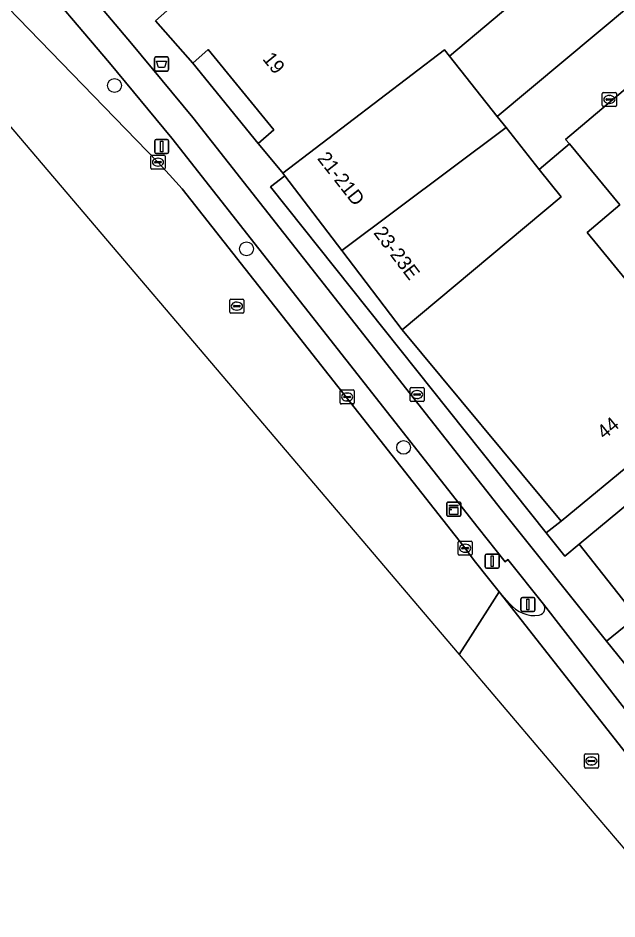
# Model space of a CAD drawing. Extents: x 161087 to 161926, y 382572 to 383873.
# Drawn here: x 161275.9 to 161318.5, y 383048.2 to 383112.2 of the extents above; entities that cross this region are included whole.
import ezdxf

# ---------------------------------------------------------------- set-up
doc = ezdxf.new("R2010")
doc.units = 0
for name, color, linetype in [('IMGEO_Afvalbak', 7, 'Continuous'), ('IMGEO_Berm_groen', 7, 'Continuous'), ('IMGEO_Boom', 7, 'Continuous'), ('IMGEO_Brandkraan', 7, 'Continuous'), ('IMGEO_Fietspad_gesloten', 7, 'Continuous'), ('IMGEO_Kast', 7, 'Continuous'), ('IMGEO_Kolk', 7, 'Continuous'), ('IMGEO_Lichtmast', 7, 'Continuous'), ('IMGEO_Pand', 7, 'Continuous'), ('IMGEO_Pand_nummerreeks', 7, 'Continuous'), ('IMGEO_Pand_overbouw', 7, 'Continuous'), ('IMGEO_Rijbaan_lokaal_gesloten', 7, 'Continuous'), ('IMGEO_Rijbaan_lokaal_open', 7, 'Continuous'), ('IMGEO_Rioolput', 7, 'Continuous'), ('IMGEO_Terreindeel_open', 7, 'Continuous'), ('IMGEO_Verkeersregelinstallatiepaal', 7, 'Continuous'), ('IMGEO_Voetgangersgebied_open', 7, 'Continuous'), ('IMGEO_Voetpad_open', 7, 'Continuous')]:
    doc.layers.add(name, color=color, linetype=linetype)

msp = doc.modelspace()

# ---------------------------------------------------------------- linework, layer by layer
at = {"layer": 'IMGEO_Afvalbak'}
for p, q in [((161285.712, 383109.459), (161286.502, 383109.459)), ((161286.502, 383109.459), (161285.712, 383109.459)), ((161285.612, 383108.559), (161285.612, 383109.359)), ((161285.612, 383109.359), (161285.612, 383108.559)), ((161286.602, 383109.359), (161286.602, 383108.559)), ((161286.602, 383108.559), (161286.602, 383109.359)), ((161286.502, 383108.459), (161285.712, 383108.459)), ((161285.712, 383108.459), (161286.502, 383108.459))]:
    msp.add_line(p, q, dxfattribs=at)
msp.add_lwpolyline([(161285.755, 383109.173), (161286.459, 383109.173), (161286.31, 383108.703), (161285.904, 383108.703), (161285.755, 383109.173)], dxfattribs=at)
for centre, start, end in [((161285.712, 383109.359), 90, 180), ((161285.712, 383109.359), 90, 180), ((161286.502, 383109.359), 0, 90), ((161286.502, 383109.359), 360, 90), ((161285.712, 383108.559), 180, 270), ((161285.712, 383108.559), 180, 270), ((161286.502, 383108.559), 270, 0), ((161286.502, 383108.559), 270, 0)]:
    msp.add_arc(centre, 0.1, start, end, dxfattribs=at)
at = {"layer": 'IMGEO_Berm_groen'}
for points in [[(161252.834, 383141.869), (161249.891, 383139.013), (161250.747, 383138.142), (161260.112, 383128.472), (161274.401, 383113.771), (161285.856, 383101.979), (161286.681, 383101.086), (161287.586, 383100.08), (161307.615, 383074.667), (161308.345, 383073.655), (161309.464, 383072.265), (161310.134, 383071.432), (161310.872, 383070.614)], [(161313.28, 383070.545), (161310.735, 383073.723), (161310.56, 383073.578), (161308.644, 383075.982), (161286.834, 383103.696), (161282.397, 383109.044), (161276.591, 383115.882)]]:
    msp.add_lwpolyline(points, dxfattribs=at)
for centre, radius, start, end in [((161312.644, 383071.988), 2.242, 217.80063, 278.38962), ((161312.872, 383070.249), 0.504, 344.59382, 35.96896), ((161312.889, 383070.252), 0.489, 279.70174, 343.73054)]:
    msp.add_arc(centre, radius, start, end, dxfattribs=at)
at = {"layer": 'IMGEO_Boom'}
for centre in [(161282.763, 383107.431), (161292.154, 383095.819), (161303.331, 383081.699)]:
    msp.add_circle(centre, 0.489, dxfattribs=at)
at = {"layer": 'IMGEO_Brandkraan'}
for p, q in [((161303.786, 383085.034), (161303.786, 383085.886)), ((161303.861, 383085.96), (161304.713, 383085.96)), ((161304.274, 383085.74), (161304.299, 383085.74)), ((161304.787, 383085.886), (161304.787, 383085.034)), ((161304.045, 383085.454), (161304.045, 383085.466)), ((161304.483, 383085.417), (161304.085, 383085.417)), ((161304.088, 383085.503), (161304.486, 383085.503)), ((161304.297, 383085.18), (161304.272, 383085.18)), ((161304.529, 383085.466), (161304.529, 383085.454)), ((161304.713, 383084.96), (161303.861, 383084.96))]:
    msp.add_line(p, q, dxfattribs=at)
for points in [[(161303.786, 383085.034), (161303.786, 383085.886)], [(161303.861, 383085.96), (161304.713, 383085.96)], [(161304.787, 383085.886), (161304.787, 383085.034)], [(161304.713, 383084.96), (161303.861, 383084.96)]]:
    msp.add_lwpolyline(points, dxfattribs=at)
for centre, radius, start, end in [((161303.863, 383085.884), 0.0765, 91.55205, 178.44795), ((161303.863, 383085.884), 0.0765, 91.55205, 178.44795), ((161304.711, 383085.884), 0.0765, 1.55205, 88.44795), ((161304.711, 383085.884), 0.0765, 1.55205, 88.44795), ((161304.085, 383085.463), 0.0403, 85.87752, 175.75265), ((161304.082, 383085.453), 0.0366, 178.93798, 274.71019), ((161304.486, 383085.46), 0.043, 264.86636, 352.45326), ((161304.49, 383085.465), 0.0386, 1.73085, 96.63898), ((161303.863, 383085.036), 0.0765, 181.55205, 268.44795), ((161303.863, 383085.036), 0.0765, 181.55205, 268.44795), ((161304.711, 383085.036), 0.0765, 271.55205, 358.44795), ((161304.711, 383085.036), 0.0765, 271.55205, 358.44795)]:
    msp.add_arc(centre, radius, start, end, dxfattribs=at)
for centre, major_axis, ratio, start_param, end_param in [((161304.273, 383085.46), (-0.387, 0.002), 0.722429, 4.712389, 7.853982), ((161304.298, 383085.46), (-0.39, 0.002), 0.717154, 1.570796, 4.712389)]:
    msp.add_ellipse(centre, major_axis=major_axis, ratio=ratio, start_param=start_param, end_param=end_param, dxfattribs=at)
at = {"layer": 'IMGEO_Fietspad_gesloten'}
msp.add_lwpolyline([(161276.591, 383115.882), (161282.397, 383109.044), (161286.834, 383103.696), (161308.644, 383075.982), (161310.56, 383073.578), (161310.735, 383073.723), (161313.28, 383070.545), (161323.08, 383057.943), (161324.746, 383059.32), (161317.769, 383067.924), (161310.282, 383077.252), (161288.336, 383105.145), (161283.981, 383110.422), (161278.277, 383117.164)], dxfattribs=at)
at = {"layer": 'IMGEO_Kast'}
for p, q in [((161306.399, 383076.891), (161306.399, 383077.732)), ((161306.399, 383077.732), (161306.399, 383076.891)), ((161306.474, 383077.816), (161307.315, 383077.816)), ((161307.315, 383077.816), (161306.474, 383077.816)), ((161307.399, 383077.741), (161307.399, 383076.9)), ((161307.399, 383076.9), (161307.399, 383077.741)), ((161307.324, 383076.816), (161306.483, 383076.816)), ((161306.483, 383076.816), (161307.324, 383076.816))]:
    msp.add_line(p, q, dxfattribs=at)
for points in [[(161306.594, 383077.606), (161307.194, 383077.606), (161307.194, 383077.521), (161306.594, 383077.521), (161306.594, 383077.606)], [(161306.594, 383077.431), (161307.194, 383077.431), (161307.194, 383076.942), (161306.594, 383076.942), (161306.594, 383077.431)]]:
    msp.add_lwpolyline(points, dxfattribs=at)
msp.add_circle((161306.678, 383077.28), 0.0377, dxfattribs=at)
for centre, start, end in [((161306.477, 383077.738), 92.4484, 184.28452), ((161306.477, 383077.738), 92.4484, 184.28452), ((161307.321, 383077.738), 2.4484, 94.28452), ((161307.321, 383077.738), 2.4484, 94.28452), ((161306.477, 383076.894), 182.4484, 274.28452), ((161306.477, 383076.894), 182.4484, 274.28452), ((161307.321, 383076.894), 272.4484, 4.28452), ((161307.321, 383076.894), 272.4484, 4.28452)]:
    msp.add_arc(centre, 0.0779, start, end, dxfattribs=at)
at = {"layer": 'IMGEO_Kolk'}
for p, q in [((161317.467, 383106.014), (161317.467, 383106.866)), ((161317.542, 383106.94), (161318.394, 383106.94)), ((161318.468, 383106.866), (161318.468, 383106.014)), ((161317.726, 383106.434), (161317.726, 383106.446)), ((161318.164, 383106.397), (161317.766, 383106.397)), ((161317.769, 383106.483), (161318.167, 383106.483)), ((161317.955, 383106.72), (161317.98, 383106.72)), ((161318.21, 383106.446), (161318.21, 383106.434)), ((161318.394, 383105.94), (161317.542, 383105.94)), ((161317.978, 383106.16), (161317.953, 383106.16)), ((161285.355, 383101.553), (161285.355, 383102.405)), ((161285.43, 383102.479), (161286.282, 383102.479)), ((161286.356, 383102.405), (161286.356, 383101.553)), ((161285.614, 383101.973), (161285.614, 383101.985)), ((161286.052, 383101.936), (161285.654, 383101.936)), ((161285.657, 383102.022), (161286.055, 383102.022)), ((161285.843, 383102.259), (161285.868, 383102.259)), ((161286.098, 383101.985), (161286.098, 383101.973)), ((161286.282, 383101.479), (161285.43, 383101.479)), ((161285.866, 383101.699), (161285.841, 383101.699)), ((161298.887, 383085.788), (161299.739, 383085.788)), ((161298.812, 383084.862), (161298.812, 383085.714)), ((161299.071, 383085.282), (161299.071, 383085.294)), ((161299.509, 383085.245), (161299.111, 383085.245)), ((161299.114, 383085.331), (161299.512, 383085.331)), ((161299.3, 383085.568), (161299.325, 383085.568)), ((161299.555, 383085.294), (161299.555, 383085.282)), ((161299.813, 383085.714), (161299.813, 383084.862)), ((161299.739, 383084.788), (161298.887, 383084.788)), ((161299.323, 383085.008), (161299.298, 383085.008)), ((161307.205, 383074.106), (161307.205, 383074.958)), ((161307.28, 383075.032), (161308.132, 383075.032)), ((161308.206, 383074.958), (161308.206, 383074.106)), ((161307.464, 383074.526), (161307.464, 383074.538)), ((161307.902, 383074.489), (161307.504, 383074.489)), ((161307.507, 383074.575), (161307.905, 383074.575)), ((161307.716, 383074.252), (161307.691, 383074.252)), ((161307.693, 383074.812), (161307.718, 383074.812)), ((161307.948, 383074.538), (161307.948, 383074.526)), ((161308.132, 383074.032), (161307.28, 383074.032))]:
    msp.add_line(p, q, dxfattribs=at)
for points in [[(161317.467, 383106.014), (161317.467, 383106.866)], [(161317.542, 383106.94), (161318.394, 383106.94)], [(161318.468, 383106.866), (161318.468, 383106.014)], [(161318.394, 383105.94), (161317.542, 383105.94)], [(161285.355, 383101.553), (161285.355, 383102.405)], [(161285.43, 383102.479), (161286.282, 383102.479)], [(161286.356, 383102.405), (161286.356, 383101.553)], [(161286.282, 383101.479), (161285.43, 383101.479)], [(161298.887, 383085.788), (161299.739, 383085.788)], [(161298.812, 383084.862), (161298.812, 383085.714)], [(161299.813, 383085.714), (161299.813, 383084.862)], [(161299.739, 383084.788), (161298.887, 383084.788)], [(161307.205, 383074.106), (161307.205, 383074.958)], [(161307.28, 383075.032), (161308.132, 383075.032)], [(161308.206, 383074.958), (161308.206, 383074.106)], [(161308.132, 383074.032), (161307.28, 383074.032)]]:
    msp.add_lwpolyline(points, dxfattribs=at)
for centre, radius, start, end in [((161317.544, 383106.864), 0.0765, 91.55205, 178.44795), ((161317.544, 383106.864), 0.0765, 91.55205, 178.44795), ((161318.392, 383106.864), 0.0765, 1.55205, 88.44795), ((161318.392, 383106.864), 0.0765, 1.55205, 88.44795), ((161317.766, 383106.443), 0.0403, 85.87752, 175.75265), ((161317.763, 383106.433), 0.0366, 178.93798, 274.71019), ((161318.167, 383106.44), 0.043, 264.86636, 352.45326), ((161318.171, 383106.445), 0.0386, 1.73085, 96.63898), ((161317.544, 383106.016), 0.0765, 181.55205, 268.44795), ((161317.544, 383106.016), 0.0765, 181.55205, 268.44795), ((161318.392, 383106.016), 0.0765, 271.55205, 358.44795), ((161318.392, 383106.016), 0.0765, 271.55205, 358.44795), ((161285.432, 383102.403), 0.0765, 91.55205, 178.44795), ((161285.432, 383102.403), 0.0765, 91.55205, 178.44795), ((161286.28, 383102.403), 0.0765, 1.55205, 88.44795), ((161286.28, 383102.403), 0.0765, 1.55205, 88.44795), ((161285.654, 383101.982), 0.0403, 85.87752, 175.75265), ((161285.651, 383101.972), 0.0366, 178.93798, 274.71019), ((161286.055, 383101.979), 0.043, 264.86636, 352.45326), ((161286.059, 383101.984), 0.0386, 1.73085, 96.63898), ((161285.432, 383101.555), 0.0765, 181.55205, 268.44795), ((161285.432, 383101.555), 0.0765, 181.55205, 268.44795), ((161286.28, 383101.555), 0.0765, 271.55205, 358.44795), ((161286.28, 383101.555), 0.0765, 271.55205, 358.44795), ((161298.889, 383085.712), 0.0765, 91.55205, 178.44795), ((161298.889, 383085.712), 0.0765, 91.55205, 178.44795), ((161299.737, 383085.712), 0.0765, 1.55205, 88.44795), ((161299.737, 383085.712), 0.0765, 1.55205, 88.44795), ((161299.111, 383085.291), 0.0403, 85.87752, 175.75265), ((161299.108, 383085.281), 0.0366, 178.93798, 274.71019), ((161299.512, 383085.288), 0.043, 264.86636, 352.45326), ((161299.516, 383085.293), 0.0386, 1.73085, 96.63898), ((161298.889, 383084.864), 0.0765, 181.55205, 268.44795), ((161298.889, 383084.864), 0.0765, 181.55205, 268.44795), ((161299.737, 383084.864), 0.0765, 271.55205, 358.44795), ((161299.737, 383084.864), 0.0765, 271.55205, 358.44795), ((161307.282, 383074.956), 0.0765, 91.55205, 178.44795), ((161307.282, 383074.956), 0.0765, 91.55205, 178.44795), ((161308.13, 383074.956), 0.0765, 1.55205, 88.44795), ((161308.13, 383074.956), 0.0765, 1.55205, 88.44795), ((161307.504, 383074.535), 0.0403, 85.87752, 175.75265), ((161307.501, 383074.525), 0.0366, 178.93798, 274.71019), ((161307.905, 383074.532), 0.043, 264.86636, 352.45326), ((161307.909, 383074.537), 0.0386, 1.73085, 96.63898), ((161307.282, 383074.108), 0.0765, 181.55205, 268.44795), ((161307.282, 383074.108), 0.0765, 181.55205, 268.44795), ((161308.13, 383074.108), 0.0765, 271.55205, 358.44795), ((161308.13, 383074.108), 0.0765, 271.55205, 358.44795)]:
    msp.add_arc(centre, radius, start, end, dxfattribs=at)
for centre, major_axis, ratio, start_param, end_param in [((161317.954, 383106.44), (-0.387, 0.002), 0.722429, 4.712389, 7.853982), ((161317.979, 383106.44), (-0.39, 0.002), 0.717154, 1.570796, 4.712389), ((161285.842, 383101.979), (-0.387, 0.002), 0.722429, 4.712389, 7.853982), ((161285.867, 383101.979), (-0.39, 0.002), 0.717154, 1.570796, 4.712389), ((161299.299, 383085.288), (-0.387, 0.002), 0.722429, 4.712389, 7.853982), ((161299.324, 383085.288), (-0.39, 0.002), 0.717154, 1.570796, 4.712389), ((161307.692, 383074.532), (-0.387, 0.002), 0.722429, 4.712389, 7.853982), ((161307.717, 383074.532), (-0.39, 0.002), 0.717154, 1.570796, 4.712389)]:
    msp.add_ellipse(centre, major_axis=major_axis, ratio=ratio, start_param=start_param, end_param=end_param, dxfattribs=at)
at = {"layer": 'IMGEO_Lichtmast'}
for p, q in [((161285.625, 383102.698), (161285.625, 383103.498)), ((161285.625, 383103.498), (161285.625, 383102.698)), ((161285.725, 383103.598), (161286.515, 383103.598)), ((161286.515, 383103.598), (161285.725, 383103.598)), ((161286.615, 383103.498), (161286.615, 383102.698)), ((161286.615, 383102.698), (161286.615, 383103.498)), ((161286.515, 383102.598), (161285.725, 383102.598)), ((161285.725, 383102.598), (161286.515, 383102.598)), ((161309.135, 383073.209), (161309.135, 383074.009)), ((161309.135, 383074.009), (161309.135, 383073.209)), ((161309.235, 383074.109), (161310.025, 383074.109)), ((161310.025, 383074.109), (161309.235, 383074.109)), ((161310.125, 383074.009), (161310.125, 383073.209)), ((161310.125, 383073.209), (161310.125, 383074.009)), ((161310.025, 383073.109), (161309.235, 383073.109)), ((161309.235, 383073.109), (161310.025, 383073.109))]:
    msp.add_line(p, q, dxfattribs=at)
for points in [[(161286.045, 383103.473), (161286.195, 383103.473), (161286.195, 383102.723), (161286.045, 383102.723), (161286.045, 383103.473)], [(161309.555, 383073.984), (161309.705, 383073.984), (161309.705, 383073.234), (161309.555, 383073.234), (161309.555, 383073.984)]]:
    msp.add_lwpolyline(points, dxfattribs=at)
for centre, start, end in [((161285.725, 383103.498), 90, 180), ((161285.725, 383103.498), 90, 180), ((161286.515, 383103.498), 0, 90), ((161286.515, 383103.498), 360, 90), ((161285.725, 383102.698), 180, 270), ((161285.725, 383102.698), 180, 270), ((161286.515, 383102.698), 270, 0), ((161286.515, 383102.698), 270, 0), ((161309.235, 383074.009), 90, 180), ((161309.235, 383074.009), 90, 180), ((161310.025, 383074.009), 0, 90), ((161310.025, 383074.009), 360, 90), ((161309.235, 383073.209), 180, 270), ((161309.235, 383073.209), 180, 270), ((161310.025, 383073.209), 270, 0), ((161310.025, 383073.209), 270, 0)]:
    msp.add_arc(centre, 0.1, start, end, dxfattribs=at)
at = {"layer": 'IMGEO_Pand'}
for points in [[(161294.742, 383101.191), (161306.233, 383109.974), (161306.597, 383109.514), (161315.91, 383117.352), (161328.147, 383127.651), (161321.746, 383135.741), (161318.155, 383140.007), (161303.657, 383127.806), (161297.243, 383122.411), (161296.75, 383123.041), (161284.685, 383113.393), (161285.039, 383113), (161286.136, 383113.965), (161286.895, 383113.101), (161285.682, 383112.035), (161288.325, 383109.028), (161289.427, 383109.997), (161294.094, 383104.286), (161292.975, 383103.318), (161294.672, 383101.283)], [(161325.68, 383085.643), (161336.573, 383094.624), (161323.371, 383110.78), (161314.857, 383103.599), (161315.131, 383103.273), (161318.705, 383098.955), (161316.388, 383096.985)], [(161294.742, 383101.191), (161294.883, 383101.006), (161298.925, 383095.704), (161310.619, 383104.438), (161309.985, 383105.238), (161306.597, 383109.514), (161306.233, 383109.974)], [(161298.925, 383095.704), (161303.223, 383090.065), (161314.545, 383099.513), (161312.979, 383101.462), (161310.619, 383104.438)], [(161325.68, 383085.643), (161316.388, 383096.985), (161318.705, 383098.955), (161315.131, 383103.273), (161312.979, 383101.462), (161314.545, 383099.513), (161303.223, 383090.065), (161314.528, 383076.448)]]:
    msp.add_lwpolyline(points, close=True, dxfattribs=at)
at = {"layer": 'IMGEO_Pand_overbouw'}
msp.add_lwpolyline([(161292.975, 383103.318), (161294.094, 383104.286), (161289.427, 383109.997), (161288.325, 383109.028)], close=True, dxfattribs=at)
at = {"layer": 'IMGEO_Rijbaan_lokaal_gesloten'}
msp.add_lwpolyline([(161307.272, 383066.988), (161308.081, 383068.244), (161310.134, 383071.432), (161309.464, 383072.265), (161308.345, 383073.655), (161307.615, 383074.667), (161287.586, 383100.08), (161286.681, 383101.086), (161285.856, 383101.979), (161274.401, 383113.771), (161260.112, 383128.472), (161250.747, 383138.142), (161249.891, 383139.013), (161245.035, 383144.043), (161237.305, 383152.019), (161236.492, 383152.832), (161235.276, 383151.613), (161307.272, 383066.988)], dxfattribs=at)
msp.add_lwpolyline([(161307.272, 383066.988), (161316.471, 383056.176), (161319.897, 383052.149), (161322.958, 383048.175), (161323.369, 383048.79), (161325.438, 383051.889), (161323.275, 383054.641), (161322.567, 383055.613), (161310.134, 383071.432), (161308.081, 383068.244)], close=True, dxfattribs=at)
at = {"layer": 'IMGEO_Rijbaan_lokaal_open'}
msp.add_lwpolyline([(161309.985, 383105.238), (161310.619, 383104.438), (161312.979, 383101.462), (161315.131, 383103.273), (161314.857, 383103.599), (161323.371, 383110.78), (161328.949, 383115.484), (161334.699, 383120.333), (161331.884, 383123.579), (161319.475, 383113.135)], close=True, dxfattribs=at)
msp.add_lwpolyline([(161362.829, 383095.814), (161364.77, 383097.35), (161362.866, 383099.876), (161359.598, 383104.154), (161357.76, 383102.637), (161353.934, 383096.833), (161331.379, 383078.376), (161324.754, 383073.591), (161319.89, 383069.645), (161317.769, 383067.924), (161324.746, 383059.32), (161325.561, 383058.315)], dxfattribs=at)
at = {"layer": 'IMGEO_Rioolput'}
for p, q in [((161290.969, 383091.32), (161290.969, 383092.172)), ((161291.044, 383092.246), (161291.896, 383092.246)), ((161291.97, 383092.172), (161291.97, 383091.32)), ((161291.228, 383091.74), (161291.228, 383091.752)), ((161291.666, 383091.703), (161291.268, 383091.703)), ((161291.271, 383091.789), (161291.669, 383091.789)), ((161291.457, 383092.026), (161291.482, 383092.026)), ((161291.712, 383091.752), (161291.712, 383091.74)), ((161291.896, 383091.246), (161291.044, 383091.246)), ((161291.48, 383091.466), (161291.455, 383091.466)), ((161316.188, 383058.982), (161316.188, 383059.834)), ((161316.263, 383059.908), (161317.115, 383059.908)), ((161316.676, 383059.688), (161316.701, 383059.688)), ((161317.189, 383059.834), (161317.189, 383058.982)), ((161317.115, 383058.908), (161316.263, 383058.908)), ((161316.447, 383059.402), (161316.447, 383059.414)), ((161316.885, 383059.365), (161316.487, 383059.365)), ((161316.49, 383059.451), (161316.888, 383059.451)), ((161316.699, 383059.128), (161316.674, 383059.128)), ((161316.931, 383059.414), (161316.931, 383059.402))]:
    msp.add_line(p, q, dxfattribs=at)
for points in [[(161290.969, 383091.32), (161290.969, 383092.172)], [(161291.044, 383092.246), (161291.896, 383092.246)], [(161291.97, 383092.172), (161291.97, 383091.32)], [(161291.896, 383091.246), (161291.044, 383091.246)], [(161316.188, 383058.982), (161316.188, 383059.834)], [(161316.263, 383059.908), (161317.115, 383059.908)], [(161317.189, 383059.834), (161317.189, 383058.982)], [(161317.115, 383058.908), (161316.263, 383058.908)]]:
    msp.add_lwpolyline(points, dxfattribs=at)
for centre, radius, start, end in [((161291.046, 383092.17), 0.0765, 91.55205, 178.44795), ((161291.046, 383092.17), 0.0765, 91.55205, 178.44795), ((161291.894, 383092.17), 0.0765, 1.55205, 88.44795), ((161291.894, 383092.17), 0.0765, 1.55205, 88.44795), ((161291.268, 383091.749), 0.0403, 85.87752, 175.75265), ((161291.265, 383091.739), 0.0366, 178.93798, 274.71019), ((161291.669, 383091.746), 0.043, 264.86636, 352.45326), ((161291.673, 383091.751), 0.0386, 1.73085, 96.63898), ((161291.046, 383091.322), 0.0765, 181.55205, 268.44795), ((161291.046, 383091.322), 0.0765, 181.55205, 268.44795), ((161291.894, 383091.322), 0.0765, 271.55205, 358.44795), ((161291.894, 383091.322), 0.0765, 271.55205, 358.44795), ((161316.265, 383059.832), 0.0765, 91.55205, 178.44795), ((161316.265, 383059.832), 0.0765, 91.55205, 178.44795), ((161317.113, 383059.832), 0.0765, 1.55205, 88.44795), ((161317.113, 383059.832), 0.0765, 1.55205, 88.44795), ((161316.265, 383058.984), 0.0765, 181.55205, 268.44795), ((161316.265, 383058.984), 0.0765, 181.55205, 268.44795), ((161316.487, 383059.411), 0.0403, 85.87752, 175.75265), ((161316.484, 383059.401), 0.0366, 178.93798, 274.71019), ((161316.888, 383059.408), 0.043, 264.86636, 352.45326), ((161316.892, 383059.413), 0.0386, 1.73085, 96.63898), ((161317.113, 383058.984), 0.0765, 271.55205, 358.44795), ((161317.113, 383058.984), 0.0765, 271.55205, 358.44795)]:
    msp.add_arc(centre, radius, start, end, dxfattribs=at)
for centre, major_axis, ratio, start_param, end_param in [((161291.456, 383091.746), (-0.387, 0.002), 0.722429, 4.712389, 7.853982), ((161291.481, 383091.746), (-0.39, 0.002), 0.717154, 1.570796, 4.712389), ((161316.675, 383059.408), (-0.387, 0.002), 0.722429, 4.712389, 7.853982), ((161316.7, 383059.408), (-0.39, 0.002), 0.717154, 1.570796, 4.712389)]:
    msp.add_ellipse(centre, major_axis=major_axis, ratio=ratio, start_param=start_param, end_param=end_param, dxfattribs=at)
at = {"layer": 'IMGEO_Terreindeel_open'}
for points in [[(161319.475, 383113.135), (161316.874, 383116.227), (161315.91, 383117.352), (161306.597, 383109.514), (161309.985, 383105.238)], [(161289.427, 383109.997), (161288.325, 383109.028), (161292.975, 383103.318), (161294.094, 383104.286)]]:
    msp.add_lwpolyline(points, close=True, dxfattribs=at)
at = {"layer": 'IMGEO_Verkeersregelinstallatiepaal'}
for p, q in [((161311.776, 383071.037), (161312.566, 383071.037)), ((161312.566, 383071.037), (161311.776, 383071.037)), ((161311.676, 383070.137), (161311.676, 383070.937)), ((161311.676, 383070.937), (161311.676, 383070.137)), ((161312.666, 383070.937), (161312.666, 383070.137)), ((161312.666, 383070.137), (161312.666, 383070.937)), ((161312.566, 383070.037), (161311.776, 383070.037)), ((161311.776, 383070.037), (161312.566, 383070.037))]:
    msp.add_line(p, q, dxfattribs=at)
msp.add_lwpolyline([(161312.096, 383070.912), (161312.246, 383070.912), (161312.246, 383070.162), (161312.096, 383070.162), (161312.096, 383070.912)], dxfattribs=at)
for centre, start, end in [((161311.776, 383070.937), 90, 180), ((161311.776, 383070.937), 90, 180), ((161312.566, 383070.937), 0, 90), ((161312.566, 383070.937), 360, 90), ((161311.776, 383070.137), 180, 270), ((161311.776, 383070.137), 180, 270), ((161312.566, 383070.137), 270, 0), ((161312.566, 383070.137), 270, 0)]:
    msp.add_arc(centre, 0.1, start, end, dxfattribs=at)
at = {"layer": 'IMGEO_Voetgangersgebied_open'}
for points in [[(161353.934, 383096.833), (161357.76, 383102.637), (161355.325, 383105.517), (161357.325, 383107.176), (161353.567, 383112.777), (161350.565, 383110.309), (161346.896, 383114.722), (161346.807, 383114.65), (161342.789, 383111.42), (161342.668, 383111.323), (161349.672, 383102.844), (161315.817, 383074.812), (161319.89, 383069.645), (161324.754, 383073.591), (161331.379, 383078.376)], [(161349.672, 383102.844), (161342.668, 383111.323), (161342.3, 383111.027), (161348.002, 383104.048), (161342.197, 383099.261), (161336.573, 383094.624), (161325.68, 383085.643), (161314.528, 383076.448), (161313.477, 383075.634), (161314.803, 383073.972), (161315.817, 383074.812)]]:
    msp.add_lwpolyline(points, close=True, dxfattribs=at)
at = {"layer": 'IMGEO_Voetpad_open'}
for points in [[(161278.277, 383117.164), (161283.981, 383110.422), (161288.336, 383105.145), (161310.282, 383077.252), (161317.769, 383067.924), (161319.89, 383069.645), (161315.817, 383074.812)], [(161315.817, 383074.812), (161314.803, 383073.972), (161313.477, 383075.634), (161293.859, 383100.22), (161294.883, 383101.006), (161294.742, 383101.191), (161294.672, 383101.283), (161292.975, 383103.318), (161288.325, 383109.028), (161285.682, 383112.035), (161286.895, 383113.101)], [(161310.872, 383070.614), (161310.134, 383071.432), (161322.567, 383055.613)], [(161323.08, 383057.943), (161313.28, 383070.545)]]:
    msp.add_lwpolyline(points, dxfattribs=at)
msp.add_lwpolyline([(161303.223, 383090.065), (161298.925, 383095.704), (161294.883, 383101.006), (161293.859, 383100.22), (161313.477, 383075.634), (161314.528, 383076.448)], close=True, dxfattribs=at)
for centre, radius, start, end in [((161312.644, 383071.988), 2.242, 217.80063, 278.38962), ((161312.872, 383070.249), 0.504, 344.59382, 35.96896), ((161312.889, 383070.252), 0.489, 279.70174, 343.73054)]:
    msp.add_arc(centre, radius, start, end, dxfattribs=at)

# ---------------------------------------------------------------- texts
at = {"layer": 'IMGEO_Pand_nummerreeks'}
for s, rotation, p in [('19', 309.25552, (161293.246, 383109.306)), ('21-21D', 308.11384, (161297.145, 383102.233)), ('23-23E', 307.31672, (161301.148, 383096.944)), ('44', 39.39344, (161317.605, 383082.236))]:
    msp.add_text(s, height=1, rotation=rotation, dxfattribs=at).set_placement(p)

doc.saveas('drawing.dxf')
